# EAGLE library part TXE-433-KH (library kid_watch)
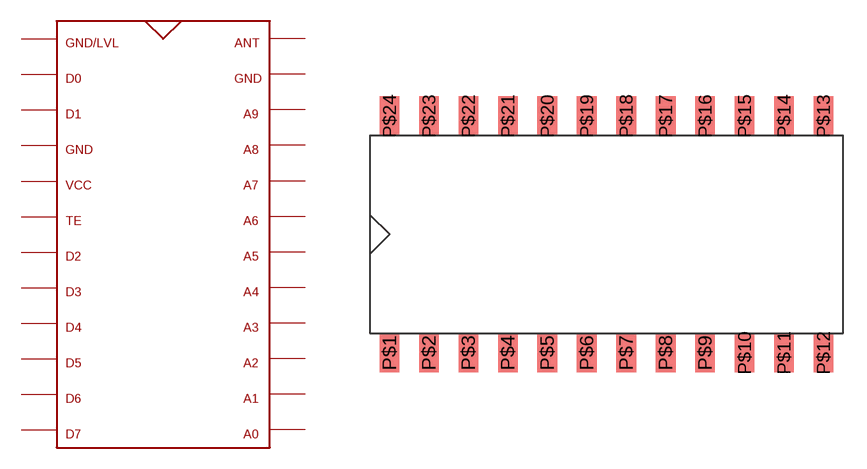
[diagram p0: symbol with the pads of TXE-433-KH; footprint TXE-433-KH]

Designator prefix -

## TXE-433-KH  [TXE-433-KH]
P$1  P$1
P$2  P$2
P$3  P$3
P$4  P$4
P$5  P$5
P$6  P$6
P$7  P$7
P$8  P$8
P$9  P$9
P$10  P$10
P$11  P$11
P$12  P$12
P$13  P$13
P$14  P$14
P$15  P$15
P$16  P$16
P$17  P$17
P$18  P$18
P$19  P$19
P$20  P$20
P$21  P$21
P$22  P$22
P$23  P$23
P$24  P$24

## Footprint TXE-433-KH (pad centres in mm)
smd 1.27 x 2.54: P$1 0,0; P$2 2.54,0; P$3 5.08,0; P$4 7.62,0; P$5 10.16,0; P$6 12.7,0; P$7 15.24,0; P$8 17.78,0; P$9 20.32,0; P$10 22.86,0; P$11 25.4,0; P$12 27.94,0; P$13 27.94,15.24; P$14 25.4,15.24; P$15 22.86,15.24; P$16 20.32,15.24; P$17 17.78,15.24; P$18 15.24,15.24; P$19 12.7,15.24; P$20 10.16,15.24; P$21 7.62,15.24; P$22 5.08,15.24; P$23 2.54,15.24; P$24 0,15.24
